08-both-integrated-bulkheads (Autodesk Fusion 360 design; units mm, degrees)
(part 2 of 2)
sketch "B Facet 180 Triangle 4" plane through (0, -75, 0) normal (0, -1, 0) x axis (-1, 0, 0)
  line L1 (124, -27.066) -> (60.9665, 27.066)
  line L2 (124, 27.066) -> (124, -27.066)
  line L3 (60.9665, 27.066) -> (124, 27.066)
  line L4 (120, -18.3583) -> (71.7639, 23.066)
  line L5 (120, 23.066) -> (120, -18.3583)
  line L6 (71.7639, 23.066) -> (120, 23.066)
  point P1 (0, 0)
  point P2 (60.9665, 27.066)
  point P3 (124, -27.066)
  point P4 (124, 27.066)
  dimension "d486" distance P1 P2 = 60.9665 (= "Linear Dimension-2")
  dimension "d487" distance P1 P2 = 27.066 (= "Linear Dimension-3")
  dimension "d488" distance P1 P3 = 124 (= "Linear Dimension-4")
  dimension "d489" distance P1 P3 = 27.066 (= "Linear Dimension-5")
  dimension "d490" distance P1 P4 = 124 (= "Linear Dimension-6")
  dimension "d491" distance P1 P4 = 27.066 (= "Linear Dimension-7")
  dimension "d492" = -4 (= "-memberWidth / 2")
extrude "Extrude15" cut sketch "B Facet 180 Triangle 4" profile of L5 L6 L4 against normal blind 4.7 (magnitude of "-( wall + 0.2 mm )")
fillet "Fillet5" radius 1.5 (= "apertureRadius")
work_plane "WorkPlane11" RotateAngle 135 ExtraOffset 0
work_plane "WorkPlane12" AlongDistance 75 (= "bodyWidth / 2") ExtraOffset 0
sketch "B Facet 225 Triangle 1" plane through (0, -53.033, -53.033) normal (0, -0.7071, -0.7071) x axis (1, 0, 0)
  line L1 (23.9949, -27.066) -> (62.2721, 27.066)
  line L2 (0.1814, 27.066) -> (23.9949, -27.066)
  line L3 (62.2721, 27.066) -> (0.1814, 27.066)
  line L4 (24.81, -18.9852) -> (54.5447, 23.066)
  line L5 (6.311, 23.066) -> (24.81, -18.9852)
  line L6 (54.5447, 23.066) -> (6.311, 23.066)
  point P1 (0, 0)
  point P2 (62.2721, 27.066)
  point P3 (23.9949, -27.066)
  point P4 (0.1814, 27.066)
  dimension "d501" distance P1 P2 = 62.2721 (= "Linear Dimension-2")
  dimension "d502" distance P1 P2 = 27.066 (= "Linear Dimension-3")
  dimension "d503" distance P1 P3 = 23.9949 (= "Linear Dimension-4")
  dimension "d504" distance P1 P3 = 27.066 (= "Linear Dimension-5")
  dimension "d505" distance P1 P4 = 0.1814 (= "Linear Dimension-6")
  dimension "d506" distance P1 P4 = 27.066 (= "Linear Dimension-7")
  dimension "d507" = 4 (= "memberWidth / 2")
extrude "Extrude16" cut sketch "B Facet 225 Triangle 1" profile of L5 L6 L4 against normal blind 4.7 (magnitude of "-( wall + 0.2 mm )")
sketch "B Facet 225 Triangle 2" plane through (0, -53.033, -53.033) normal (0, -0.7071, -0.7071) x axis (1, 0, 0)
  line L1 (0.1814, 27.066) -> (23.9949, -27.066)
  line L2 (-74.6684, -27.066) -> (0.1814, 27.066)
  line L3 (23.9949, -27.066) -> (-74.6684, -27.066)
  line L4 (-1.4863, 20.9235) -> (17.8653, -23.066)
  line L5 (-62.3117, -23.066) -> (-1.4863, 20.9235)
  line L6 (17.8653, -23.066) -> (-62.3117, -23.066)
  point P1 (0, 0)
  point P2 (23.9949, -27.066)
  point P3 (0.1814, 27.066)
  point P4 (-74.6684, -27.066)
  dimension "d510" distance P1 P2 = 23.9949 (= "Linear Dimension-2")
  dimension "d511" distance P1 P2 = 27.066 (= "Linear Dimension-3")
  dimension "d512" distance P1 P3 = 0.1814 (= "Linear Dimension-4")
  dimension "d513" distance P1 P3 = 27.066 (= "Linear Dimension-5")
  dimension "d514" distance P1 P4 = 74.6684 (= "Linear Dimension-6")
  dimension "d515" distance P1 P4 = 27.066 (= "Linear Dimension-7")
  dimension "d516" = -4 (= "-memberWidth / 2")
extrude "Extrude17" cut sketch "B Facet 225 Triangle 2" profile of L5 L6 L4 against normal blind 4.7 (magnitude of "-( wall + 0.2 mm )")
sketch "B Facet 225 Triangle 3" plane through (0, -53.033, -53.033) normal (0, -0.7071, -0.7071) x axis (1, 0, 0)
  line L1 (-74.6684, -27.066) -> (0.1814, 27.066)
  line L2 (-124, 27.066) -> (-74.6684, -27.066)
  line L3 (0.1814, 27.066) -> (-124, 27.066)
  line L4 (-74.1179, -21.7315) -> (-12.1753, 23.066)
  line L5 (-114.9429, 23.066) -> (-74.1179, -21.7315)
  line L6 (-12.1753, 23.066) -> (-114.9429, 23.066)
  point P1 (0, 0)
  point P2 (0.1814, 27.066)
  point P3 (-74.6684, -27.066)
  point P4 (-124, 27.066)
  dimension "d519" distance P1 P2 = 0.1814 (= "Linear Dimension-2")
  dimension "d520" distance P1 P2 = 27.066 (= "Linear Dimension-3")
  dimension "d521" distance P1 P3 = 74.6684 (= "Linear Dimension-4")
  dimension "d522" distance P1 P3 = 27.066 (= "Linear Dimension-5")
  dimension "d523" distance P1 P4 = 124 (= "Linear Dimension-6")
  dimension "d524" distance P1 P4 = 27.066 (= "Linear Dimension-7")
  dimension "d525" = 4 (= "memberWidth / 2")
extrude "Extrude18" cut sketch "B Facet 225 Triangle 3" profile of L5 L6 L4 against normal blind 4.7 (magnitude of "-( wall + 0.2 mm )")
sketch "B Facet 225 Triangle 4" plane through (0, -53.033, -53.033) normal (0, -0.7071, -0.7071) x axis (1, 0, 0)
  line L1 (-124, 27.066) -> (-74.6684, -27.066)
  line L2 (-124, -27.066) -> (-124, 27.066)
  line L3 (-74.6684, -27.066) -> (-124, -27.066)
  line L4 (-120, 16.7383) -> (-83.7255, -23.066)
  line L5 (-120, -23.066) -> (-120, 16.7383)
  line L6 (-83.7255, -23.066) -> (-120, -23.066)
  point P1 (0, 0)
  point P2 (-74.6684, -27.066)
  point P3 (-124, 27.066)
  point P4 (-124, -27.066)
  dimension "d528" distance P1 P2 = 74.6684 (= "Linear Dimension-2")
  dimension "d529" distance P1 P2 = 27.066 (= "Linear Dimension-3")
  dimension "d530" distance P1 P3 = 124 (= "Linear Dimension-4")
  dimension "d531" distance P1 P3 = 27.066 (= "Linear Dimension-5")
  dimension "d532" distance P1 P4 = 124 (= "Linear Dimension-6")
  dimension "d533" distance P1 P4 = 27.066 (= "Linear Dimension-7")
  dimension "d534" = -4 (= "-memberWidth / 2")
extrude "Extrude19" cut sketch "B Facet 225 Triangle 4" profile of L5 L6 L4 against normal blind 4.7 (magnitude of "-( wall + 0.2 mm )")
fillet "Fillet6" radius 1.5 (= "apertureRadius")
work_plane "WorkPlane13" RotateAngle 180 ExtraOffset 0
work_plane "WorkPlane14" AlongDistance 75 (= "bodyWidth / 2") ExtraOffset 0
sketch "B Facet 270 Triangle 1" plane through (0, 0, -75) normal (0, 0, -1) x axis (-1, 0, 0)
  line L1 (36.9655, 27.066) -> (-17.1665, -27.066)
  line L2 (53.4167, -27.066) -> (36.9655, 27.066)
  line L3 (-17.1665, -27.066) -> (53.4167, -27.066)
  line L4 (35.0777, 19.5214) -> (-7.5097, -23.066)
  line L5 (48.0205, -23.066) -> (35.0777, 19.5214)
  line L6 (-7.5097, -23.066) -> (48.0205, -23.066)
  point P1 (0, 0)
  point P2 (-17.1665, -27.066)
  point P3 (36.9655, 27.066)
  point P4 (53.4167, -27.066)
  dimension "d543" distance P1 P2 = 17.1665 (= "Linear Dimension-2")
  dimension "d544" distance P1 P2 = 27.066 (= "Linear Dimension-3")
  dimension "d545" distance P1 P3 = 36.9655 (= "Linear Dimension-4")
  dimension "d546" distance P1 P3 = 27.066 (= "Linear Dimension-5")
  dimension "d547" distance P1 P4 = 53.4167 (= "Linear Dimension-6")
  dimension "d548" distance P1 P4 = 27.066 (= "Linear Dimension-7")
  dimension "d549" = 4 (= "memberWidth / 2")
extrude "Extrude20" cut sketch "B Facet 270 Triangle 1" profile of L5 L6 L4 against normal blind 4.7 (magnitude of "-( wall + 0.2 mm )")
sketch "B Facet 270 Triangle 2" plane through (0, 0, -75) normal (0, 0, -1) x axis (-1, 0, 0)
  line L1 (53.4167, -27.066) -> (36.9655, 27.066)
  line L2 (124, 27.066) -> (53.4167, -27.066)
  line L3 (36.9655, 27.066) -> (124, 27.066)
  line L4 (55.5648, -20.3777) -> (42.3618, 23.066)
  line L5 (112.2115, 23.066) -> (55.5648, -20.3777)
  line L6 (42.3618, 23.066) -> (112.2115, 23.066)
  point P1 (0, 0)
  point P2 (36.9655, 27.066)
  point P3 (53.4167, -27.066)
  point P4 (124, 27.066)
  dimension "d552" distance P1 P2 = 36.9655 (= "Linear Dimension-2")
  dimension "d553" distance P1 P2 = 27.066 (= "Linear Dimension-3")
  dimension "d554" distance P1 P3 = 53.4167 (= "Linear Dimension-4")
  dimension "d555" distance P1 P3 = 27.066 (= "Linear Dimension-5")
  dimension "d556" distance P1 P4 = 124 (= "Linear Dimension-6")
  dimension "d557" distance P1 P4 = 27.066 (= "Linear Dimension-7")
  dimension "d558" = -4 (= "-memberWidth / 2")
extrude "Extrude21" cut sketch "B Facet 270 Triangle 2" profile of L5 L6 L4 against normal blind 4.7 (magnitude of "-( wall + 0.2 mm )")
sketch "B Facet 270 Triangle 3" plane through (0, 0, -75) normal (0, 0, -1) x axis (-1, 0, 0)
  line L1 (124, 27.066) -> (53.4167, -27.066)
  line L2 (124, -27.066) -> (124, 27.066)
  line L3 (53.4167, -27.066) -> (124, -27.066)
  line L4 (120, 18.9574) -> (65.2053, -23.066)
  line L5 (120, -23.066) -> (120, 18.9574)
  line L6 (65.2053, -23.066) -> (120, -23.066)
  point P1 (0, 0)
  point P2 (53.4167, -27.066)
  point P3 (124, 27.066)
  point P4 (124, -27.066)
  dimension "d561" distance P1 P2 = 53.4167 (= "Linear Dimension-2")
  dimension "d562" distance P1 P2 = 27.066 (= "Linear Dimension-3")
  dimension "d563" distance P1 P3 = 124 (= "Linear Dimension-4")
  dimension "d564" distance P1 P3 = 27.066 (= "Linear Dimension-5")
  dimension "d565" distance P1 P4 = 124 (= "Linear Dimension-6")
  dimension "d566" distance P1 P4 = 27.066 (= "Linear Dimension-7")
  dimension "d567" = 4 (= "memberWidth / 2")
extrude "Extrude22" cut sketch "B Facet 270 Triangle 3" profile of L5 L6 L4 against normal blind 4.7 (magnitude of "-( wall + 0.2 mm )")
fillet "Fillet7" radius 1.5 (= "apertureRadius")
work_plane "WorkPlane15" RotateAngle 225 ExtraOffset 0
work_plane "WorkPlane16" AlongDistance 75 (= "bodyWidth / 2") ExtraOffset 0
sketch "B Facet 315 Triangle 1" plane through (0, 53.033, -53.033) normal (0, 0.7071, -0.7071) x axis (1, 0, 0)
  line L1 (-82.0711, -27.066) -> (-43.7939, 27.066)
  line L2 (-124, 27.066) -> (-82.0711, -27.066)
  line L3 (-43.7939, 27.066) -> (-124, 27.066)
  line L4 (-82.2175, -20.3449) -> (-51.5213, 23.066)
  line L5 (-115.8422, 23.066) -> (-82.2175, -20.3449)
  line L6 (-51.5213, 23.066) -> (-115.8422, 23.066)
  point P1 (0, 0)
  point P2 (-43.7939, 27.066)
  point P3 (-82.0711, -27.066)
  point P4 (-124, 27.066)
  dimension "d576" distance P1 P2 = 43.7939 (= "Linear Dimension-2")
  dimension "d577" distance P1 P2 = 27.066 (= "Linear Dimension-3")
  dimension "d578" distance P1 P3 = 82.0711 (= "Linear Dimension-4")
  dimension "d579" distance P1 P3 = 27.066 (= "Linear Dimension-5")
  dimension "d580" distance P1 P4 = 124 (= "Linear Dimension-6")
  dimension "d581" distance P1 P4 = 27.066 (= "Linear Dimension-7")
  dimension "d582" = 4 (= "memberWidth / 2")
extrude "Extrude23" cut sketch "B Facet 315 Triangle 1" profile of L5 L6 L4 against normal blind 4.7 (magnitude of "-( wall + 0.2 mm )")
sketch "B Facet 315 Triangle 2" plane through (0, 53.033, -53.033) normal (0, 0.7071, -0.7071) x axis (1, 0, 0)
  line L1 (-124, 27.066) -> (-82.0711, -27.066)
  line L2 (-124, -27.066) -> (-124, 27.066)
  line L3 (-82.0711, -27.066) -> (-124, -27.066)
  line L4 (-120, 15.3697) -> (-90.2289, -23.066)
  line L5 (-120, -23.066) -> (-120, 15.3697)
  line L6 (-90.2289, -23.066) -> (-120, -23.066)
  point P1 (0, 0)
  point P2 (-82.0711, -27.066)
  point P3 (-124, 27.066)
  point P4 (-124, -27.066)
  dimension "d585" distance P1 P2 = 82.0711 (= "Linear Dimension-2")
  dimension "d586" distance P1 P2 = 27.066 (= "Linear Dimension-3")
  dimension "d587" distance P1 P3 = 124 (= "Linear Dimension-4")
  dimension "d588" distance P1 P3 = 27.066 (= "Linear Dimension-5")
  dimension "d589" distance P1 P4 = 124 (= "Linear Dimension-6")
  dimension "d590" distance P1 P4 = 27.066 (= "Linear Dimension-7")
  dimension "d591" = -4 (= "-memberWidth / 2")
extrude "Extrude24" cut sketch "B Facet 315 Triangle 2" profile of L5 L6 L4 against normal blind 4.7 (magnitude of "-( wall + 0.2 mm )")
fillet "Fillet8" radius 1.5 (= "apertureRadius")
work_plane "WorkPlane17" AlongDistance 0.5 (= "qFront") ExtraOffset 0
sketch "A Central Carrier sketch" plane through (0.3536, 0.3536, 0) normal (0.7071, 0.7071, 0) x axis (0, 0, 1)
  circle C1 centre (0, 0) radius 26
  dimension "d598" diameter C1 = 52 (= "carrierOD")
extrude "Extrude25" new body sketch "A Central Carrier sketch" along normal blind 18 (= "spokeDepth")
work_plane "WorkPlane18" AlongDistance 0.5 (= "qFront") ExtraOffset 0
sketch "A Spoke 1 Profile" plane through (0.3536, 0.3536, 0) normal (0.7071, 0.7071, 0) x axis (0, 0, 1)
  line L1 (37.3643, -145.3579) -> (-4.7984, -1.4054)
  line L2 (46.9611, -142.547) -> (37.3643, -145.3579)
  line L3 (4.7984, 1.4054) -> (46.9611, -142.547)
  line L4 (-4.7984, -1.4054) -> (4.7984, 1.4054)
  point P1 (0, 0)
  point P2 (-4.7984, -1.4054)
  point P3 (37.3643, -145.3579)
  point P4 (46.9611, -142.547)
  point P5 (4.7984, 1.4054)
  dimension "d603" distance P1 P2 = 4.7984 (= "Linear Dimension-2")
  dimension "d604" distance P1 P2 = 1.4054 (= "Linear Dimension-3")
  dimension "d605" distance P1 P3 = 37.3643 (= "Linear Dimension-4")
  dimension "d606" distance P1 P3 = 145.3579 (= "Linear Dimension-5")
  dimension "d607" distance P1 P4 = 46.9611 (= "Linear Dimension-6")
  dimension "d608" distance P1 P4 = 142.547 (= "Linear Dimension-7")
  dimension "d609" distance P1 P5 = 4.7984 (= "Linear Dimension-8")
  dimension "d610" distance P1 P5 = 1.4054 (= "Linear Dimension-9")
extrude "Extrude26" add sketch "A Spoke 1 Profile" along normal blind 18 (= "spokeDepth")
sketch "A Spoke 2 Profile" plane through (0.3536, 0.3536, 0) normal (0.7071, 0.7071, 0) x axis (0, 0, 1)
  line L1 (126.9012, -80.1317) -> (-2.5272, -4.3143)
  line L2 (131.9557, -71.5031) -> (126.9012, -80.1317)
  line L3 (2.5272, 4.3143) -> (131.9557, -71.5031)
  line L4 (-2.5272, -4.3143) -> (2.5272, 4.3143)
  point P1 (0, 0)
  point P2 (-2.5272, -4.3143)
  point P3 (126.9012, -80.1317)
  point P4 (131.9557, -71.5031)
  point P5 (2.5272, 4.3143)
  dimension "d613" distance P1 P2 = 2.5272 (= "Linear Dimension-2")
  dimension "d614" distance P1 P2 = 4.3143 (= "Linear Dimension-3")
  dimension "d615" distance P1 P3 = 126.9012 (= "Linear Dimension-4")
  dimension "d616" distance P1 P3 = 80.1317 (= "Linear Dimension-5")
  dimension "d617" distance P1 P4 = 131.9557 (= "Linear Dimension-6")
  dimension "d618" distance P1 P4 = 71.5031 (= "Linear Dimension-7")
  dimension "d619" distance P1 P5 = 2.5272 (= "Linear Dimension-8")
  dimension "d620" distance P1 P5 = 4.3143 (= "Linear Dimension-9")
extrude "Extrude27" add sketch "A Spoke 2 Profile" along normal blind 18 (= "spokeDepth")
sketch "A Spoke 3 Profile" plane through (0.3536, 0.3536, 0) normal (0.7071, 0.7071, 0) x axis (0, 0, 1)
  line L1 (131.9557, 71.5031) -> (2.5272, -4.3143)
  line L2 (126.9012, 80.1317) -> (131.9557, 71.5031)
  line L3 (-2.5272, 4.3143) -> (126.9012, 80.1317)
  line L4 (2.5272, -4.3143) -> (-2.5272, 4.3143)
  point P1 (0, 0)
  point P2 (2.5272, -4.3143)
  point P3 (131.9557, 71.5031)
  point P4 (126.9012, 80.1317)
  point P5 (-2.5272, 4.3143)
  dimension "d623" distance P1 P2 = 2.5272 (= "Linear Dimension-2")
  dimension "d624" distance P1 P2 = 4.3143 (= "Linear Dimension-3")
  dimension "d625" distance P1 P3 = 131.9557 (= "Linear Dimension-4")
  dimension "d626" distance P1 P3 = 71.5031 (= "Linear Dimension-5")
  dimension "d627" distance P1 P4 = 126.9012 (= "Linear Dimension-6")
  dimension "d628" distance P1 P4 = 80.1317 (= "Linear Dimension-7")
  dimension "d629" distance P1 P5 = 2.5272 (= "Linear Dimension-8")
  dimension "d630" distance P1 P5 = 4.3143 (= "Linear Dimension-9")
extrude "Extrude28" add sketch "A Spoke 3 Profile" along normal blind 18 (= "spokeDepth")
sketch "A Spoke 4 Profile" plane through (0.3536, 0.3536, 0) normal (0.7071, 0.7071, 0) x axis (0, 0, 1)
  line L1 (46.9611, 142.547) -> (4.7984, -1.4054)
  line L2 (37.3643, 145.3579) -> (46.9611, 142.547)
  line L3 (-4.7984, 1.4054) -> (37.3643, 145.3579)
  line L4 (4.7984, -1.4054) -> (-4.7984, 1.4054)
  point P1 (0, 0)
  point P2 (4.7984, -1.4054)
  point P3 (46.9611, 142.547)
  point P4 (37.3643, 145.3579)
  point P5 (-4.7984, 1.4054)
  dimension "d633" distance P1 P2 = 4.7984 (= "Linear Dimension-2")
  dimension "d634" distance P1 P2 = 1.4054 (= "Linear Dimension-3")
  dimension "d635" distance P1 P3 = 46.9611 (= "Linear Dimension-4")
  dimension "d636" distance P1 P3 = 142.547 (= "Linear Dimension-5")
  dimension "d637" distance P1 P4 = 37.3643 (= "Linear Dimension-6")
  dimension "d638" distance P1 P4 = 145.3579 (= "Linear Dimension-7")
  dimension "d639" distance P1 P5 = 4.7984 (= "Linear Dimension-8")
  dimension "d640" distance P1 P5 = 1.4054 (= "Linear Dimension-9")
extrude "Extrude29" add sketch "A Spoke 4 Profile" along normal blind 18 (= "spokeDepth")
sketch "A Spoke 5 Profile" plane through (0.3536, 0.3536, 0) normal (0.7071, 0.7071, 0) x axis (0, 0, 1)
  line L1 (-37.3643, 145.3579) -> (4.7984, 1.4054)
  line L2 (-46.9611, 142.547) -> (-37.3643, 145.3579)
  line L3 (-4.7984, -1.4054) -> (-46.9611, 142.547)
  line L4 (4.7984, 1.4054) -> (-4.7984, -1.4054)
  point P1 (0, 0)
  point P2 (4.7984, 1.4054)
  point P3 (-37.3643, 145.3579)
  point P4 (-46.9611, 142.547)
  point P5 (-4.7984, -1.4054)
  dimension "d643" distance P1 P2 = 4.7984 (= "Linear Dimension-2")
  dimension "d644" distance P1 P2 = 1.4054 (= "Linear Dimension-3")
  dimension "d645" distance P1 P3 = 37.3643 (= "Linear Dimension-4")
  dimension "d646" distance P1 P3 = 145.3579 (= "Linear Dimension-5")
  dimension "d647" distance P1 P4 = 46.9611 (= "Linear Dimension-6")
  dimension "d648" distance P1 P4 = 142.547 (= "Linear Dimension-7")
  dimension "d649" distance P1 P5 = 4.7984 (= "Linear Dimension-8")
  dimension "d650" distance P1 P5 = 1.4054 (= "Linear Dimension-9")
extrude "Extrude30" add sketch "A Spoke 5 Profile" along normal blind 18 (= "spokeDepth")
sketch "A Spoke 6 Profile" plane through (0.3536, 0.3536, 0) normal (0.7071, 0.7071, 0) x axis (0, 0, 1)
  line L1 (-126.9012, 80.1317) -> (2.5272, 4.3143)
  line L2 (-131.9557, 71.5031) -> (-126.9012, 80.1317)
  line L3 (-2.5272, -4.3143) -> (-131.9557, 71.5031)
  line L4 (2.5272, 4.3143) -> (-2.5272, -4.3143)
  point P1 (0, 0)
  point P2 (2.5272, 4.3143)
  point P3 (-126.9012, 80.1317)
  point P4 (-131.9557, 71.5031)
  point P5 (-2.5272, -4.3143)
  dimension "d653" distance P1 P2 = 2.5272 (= "Linear Dimension-2")
  dimension "d654" distance P1 P2 = 4.3143 (= "Linear Dimension-3")
  dimension "d655" distance P1 P3 = 126.9012 (= "Linear Dimension-4")
  dimension "d656" distance P1 P3 = 80.1317 (= "Linear Dimension-5")
  dimension "d657" distance P1 P4 = 131.9557 (= "Linear Dimension-6")
  dimension "d658" distance P1 P4 = 71.5031 (= "Linear Dimension-7")
  dimension "d659" distance P1 P5 = 2.5272 (= "Linear Dimension-8")
  dimension "d660" distance P1 P5 = 4.3143 (= "Linear Dimension-9")
extrude "Extrude31" add sketch "A Spoke 6 Profile" along normal blind 18 (= "spokeDepth")
sketch "A Spoke 7 Profile" plane through (0.3536, 0.3536, 0) normal (0.7071, 0.7071, 0) x axis (0, 0, 1)
  line L1 (-131.9557, -71.5031) -> (-2.5272, 4.3143)
  line L2 (-126.9012, -80.1317) -> (-131.9557, -71.5031)
  line L3 (2.5272, -4.3143) -> (-126.9012, -80.1317)
  line L4 (-2.5272, 4.3143) -> (2.5272, -4.3143)
  point P1 (0, 0)
  point P2 (-2.5272, 4.3143)
  point P3 (-131.9557, -71.5031)
  point P4 (-126.9012, -80.1317)
  point P5 (2.5272, -4.3143)
  dimension "d663" distance P1 P2 = 2.5272 (= "Linear Dimension-2")
  dimension "d664" distance P1 P2 = 4.3143 (= "Linear Dimension-3")
  dimension "d665" distance P1 P3 = 131.9557 (= "Linear Dimension-4")
  dimension "d666" distance P1 P3 = 71.5031 (= "Linear Dimension-5")
  dimension "d667" distance P1 P4 = 126.9012 (= "Linear Dimension-6")
  dimension "d668" distance P1 P4 = 80.1317 (= "Linear Dimension-7")
  dimension "d669" distance P1 P5 = 2.5272 (= "Linear Dimension-8")
  dimension "d670" distance P1 P5 = 4.3143 (= "Linear Dimension-9")
extrude "Extrude32" add sketch "A Spoke 7 Profile" along normal blind 18 (= "spokeDepth")
sketch "A Spoke 8 Profile" plane through (0.3536, 0.3536, 0) normal (0.7071, 0.7071, 0) x axis (0, 0, 1)
  line L1 (-46.9611, -142.547) -> (-4.7984, 1.4054)
  line L2 (-37.3643, -145.3579) -> (-46.9611, -142.547)
  line L3 (4.7984, 1.4054) -> (-37.3643, -145.3579)
  line L4 (-4.7984, 1.4054) -> (4.7984, 1.4054)
  point P1 (0, 0)
  point P2 (-4.7984, 1.4054)
  point P3 (-46.9611, -142.547)
  point P4 (-37.3643, -145.3579)
  point P5 (4.7984, 1.4054)
  dimension "d673" distance P1 P2 = 4.7984 (= "Linear Dimension-2")
  dimension "d674" distance P1 P2 = 1.4054 (= "Linear Dimension-3")
  dimension "d675" distance P1 P3 = 46.9611 (= "Linear Dimension-4")
  dimension "d676" distance P1 P3 = 142.547 (= "Linear Dimension-5")
  dimension "d677" distance P1 P4 = 37.3643 (= "Linear Dimension-6")
  dimension "d678" distance P1 P4 = 145.3579 (= "Linear Dimension-7")
  dimension "d679" distance P1 P5 = 4.7984 (= "Linear Dimension-8")
  dimension "d680" distance P1 P5 = 1.4054 (= "Linear Dimension-9")
extrude "Extrude33" add sketch "A Spoke 8 Profile" along normal blind 18 (= "spokeDepth")
sketch "Spoke Outer Envelope" plane through (0, 0, 0) normal (1, 0, 0) x axis (0, 0, -1)
  line L1 (31.066, 75) -> (75, 31.066)
  line L2 (-31.066, 75) -> (31.066, 75)
  line L3 (-75, 31.066) -> (-31.066, 75)
  line L4 (-75, -31.066) -> (-75, 31.066)
  line L5 (-31.066, -75) -> (-75, -31.066)
  line L6 (31.066, -75) -> (-31.066, -75)
  line L7 (75, -31.066) -> (31.066, -75)
  line L8 (75, 31.066) -> (75, -31.066)
  point P1 (0, 0)
  point P10 (0, 0)
  point P3 (31.066, 75)
  point P8 (31.066, -75)
  coincident P1 P10
  horizontal L2
  dimension "d683" distance P3 P8 = 150 (= "bodyWidth")
extrude "Extrude34" sketch "Spoke Outer Envelope" distance 260 (= "bodyLength")
fillet "Fillet9" radius 1 (= "rootRadius")
work_plane "WorkPlane19" AlongDistance 10.6 (= "qFrontBack") ExtraOffset 0
sketch "A Rear Carrier Clearance sketch" plane through (7.4953, 7.4953, 0) normal (0.7071, 0.7071, 0) x axis (0, 0, 1)
  circle C1 centre (0, 0) radius 23
  dimension "d690" diameter C1 = 46 (= "rearCarrierClearance")
extrude "Extrude35" cut sketch "A Rear Carrier Clearance sketch" along normal blind 18 (= "spokeDepth")
work_plane "WorkPlane20" AlongDistance 0.5 (= "qFront") ExtraOffset 0
sketch "A Seal Relief sketch" plane through (0.3536, 0.3536, 0) normal (0.7071, 0.7071, 0) x axis (0, 0, 1)
  circle C1 centre (0, 0) radius 9.75
  dimension "d695" diameter C1 = 19.5 (= "raceRelief")
extrude "Extrude36" cut sketch "A Seal Relief sketch" along normal blind 10.1 (= "frontSeatDepth + shoulder")
work_plane "WorkPlane21" AlongDistance 0.5 (= "qFront") ExtraOffset 0
sketch "A Front Bearing Seat sketch" plane through (0.3536, 0.3536, 0) normal (0.7071, 0.7071, 0) x axis (0, 0, 1)
  circle C1 centre (0, 0) radius 11.1
  dimension "d700" diameter C1 = 22.2 (= "seatDiameter")
extrude "Extrude37" cut sketch "A Front Bearing Seat sketch" along normal blind 7.1 (= "frontSeatDepth")
work_plane "WorkPlane22" AlongDistance 0.5 (= "qFront") ExtraOffset 0
sketch "A Support Bolt seed" plane through (0.3536, 0.3536, 0) normal (0.7071, 0.7071, 0) x axis (0, 0, 1)
  line L1 (17, 0) -> (0, 0)
  circle C1 centre (17, 0) radius 1.65
  point P1 (0, 0)
  point P2 (17, 0)
  horizontal L1
  dimension "d705" distance P1 P2 = 17 (= "supportCircle / 2")
  dimension "d706" diameter C1 = 3.3 (= "m3Clearance")
extrude "Extrude38" cut sketch "A Support Bolt seed" profile of C1 along normal blind 10.1 (= "frontSeatDepth + shoulder")
circular_pattern "C-Pattern1" TotalAngle 360
work_plane "WorkPlane23" AlongDistance 0.5 (= "qFront") ExtraOffset 0
sketch "A Front Bearing Boss sketch" plane through (0.3536, 0.3536, 0) normal (0.7071, 0.7071, 0) x axis (0, 0, 1)
  circle C1 centre (0, 0) radius 22
  dimension "d713" diameter C1 = 44 (= "coreOD")
chamfer "Chamfer1" distance 0.4 (= "entryChamfer")
work_plane "WorkPlane24" AlongDistance 75 (= "bodyWidth / 2") ExtraOffset 0
sketch "A Collar Driver Corridors" plane through (0, 0, 75) normal (0, 0, 1) x axis (1, 0, 0)
  circle C1 centre (6.7175, 15.9099) radius 3
  circle C2 centre (15.9099, 6.7175) radius 3
  point P1 (0, 0)
  point P2 (6.7175, 15.9099)
  point P3 (15.9099, 6.7175)
  dimension "d717" distance P1 P2 = 6.7175 (= "abs(( 16 mm + ( -6.5 mm ) ) / sqrt(2))")
  dimension "d718" distance P1 P2 = 15.9099 (= "abs(( 16 mm - ( -6.5 mm ) ) / sqrt(2))")
  dimension "d719" diameter C1 = 6
  dimension "d720" distance P1 P3 = 15.9099 (= "abs(( 16 mm + ( 6.5 mm ) ) / sqrt(2))")
  dimension "d721" distance P1 P3 = 6.7175 (= "abs(( 16 mm - ( 6.5 mm ) ) / sqrt(2))")
  dimension "d722" diameter C2 = 6
extrude "Extrude39" cut sketch "A Collar Driver Corridors" against normal blind 75 (magnitude of "-( bodyWidth / 2 )")
work_plane "WorkPlane17" ExtraOffset 0
sketch "B Central Carrier sketch" plane through (-0.3536, -0.3536, 0) normal (0.7071, 0.7071, 0) x axis (0, 0, 1)
  circle C1 centre (0, 0) radius 38
  dimension "d727" diameter C1 = 76 (= "mountOD")
extrude "Extrude25" new body sketch "B Central Carrier sketch" no distance stored
work_plane "WorkPlane18" ExtraOffset 0
sketch "B Spoke 1 Profile" plane through (-0.3536, -0.3536, 0) normal (0.7071, 0.7071, 0) x axis (0, 0, 1)
  line L1 (37.3643, -145.3579) -> (-4.7984, -1.4054)
  line L2 (46.9611, -142.547) -> (37.3643, -145.3579)
  line L3 (4.7984, 1.4054) -> (46.9611, -142.547)
  line L4 (-4.7984, -1.4054) -> (4.7984, 1.4054)
  point P1 (0, 0)
  point P2 (-4.7984, -1.4054)
  point P3 (37.3643, -145.3579)
  point P4 (46.9611, -142.547)
  point P5 (4.7984, 1.4054)
  dimension "d732" distance P1 P2 = 4.7984 (= "Linear Dimension-2")
  dimension "d733" distance P1 P2 = 1.4054 (= "Linear Dimension-3")
  dimension "d734" distance P1 P3 = 37.3643 (= "Linear Dimension-4")
  dimension "d735" distance P1 P3 = 145.3579 (= "Linear Dimension-5")
  dimension "d736" distance P1 P4 = 46.9611 (= "Linear Dimension-6")
  dimension "d737" distance P1 P4 = 142.547 (= "Linear Dimension-7")
  dimension "d738" distance P1 P5 = 4.7984 (= "Linear Dimension-8")
  dimension "d739" distance P1 P5 = 1.4054 (= "Linear Dimension-9")
extrude "Extrude26" add sketch "B Spoke 1 Profile" no distance stored
sketch "B Spoke 2 Profile" plane through (-0.3536, -0.3536, 0) normal (0.7071, 0.7071, 0) x axis (0, 0, 1)
  line L1 (126.9012, -80.1317) -> (-2.5272, -4.3143)
  line L2 (131.9557, -71.5031) -> (126.9012, -80.1317)
  line L3 (2.5272, 4.3143) -> (131.9557, -71.5031)
  line L4 (-2.5272, -4.3143) -> (2.5272, 4.3143)
  point P1 (0, 0)
  point P2 (-2.5272, -4.3143)
  point P3 (126.9012, -80.1317)
  point P4 (131.9557, -71.5031)
  point P5 (2.5272, 4.3143)
  dimension "d742" distance P1 P2 = 2.5272 (= "Linear Dimension-2")
  dimension "d743" distance P1 P2 = 4.3143 (= "Linear Dimension-3")
  dimension "d744" distance P1 P3 = 126.9012 (= "Linear Dimension-4")
  dimension "d745" distance P1 P3 = 80.1317 (= "Linear Dimension-5")
  dimension "d746" distance P1 P4 = 131.9557 (= "Linear Dimension-6")
  dimension "d747" distance P1 P4 = 71.5031 (= "Linear Dimension-7")
  dimension "d748" distance P1 P5 = 2.5272 (= "Linear Dimension-8")
  dimension "d749" distance P1 P5 = 4.3143 (= "Linear Dimension-9")
extrude "Extrude27" add sketch "B Spoke 2 Profile" no distance stored
sketch "B Spoke 3 Profile" plane through (-0.3536, -0.3536, 0) normal (0.7071, 0.7071, 0) x axis (0, 0, 1)
  line L1 (131.9557, 71.5031) -> (2.5272, -4.3143)
  line L2 (126.9012, 80.1317) -> (131.9557, 71.5031)
  line L3 (-2.5272, 4.3143) -> (126.9012, 80.1317)
  line L4 (2.5272, -4.3143) -> (-2.5272, 4.3143)
  point P1 (0, 0)
  point P2 (2.5272, -4.3143)
  point P3 (131.9557, 71.5031)
  point P4 (126.9012, 80.1317)
  point P5 (-2.5272, 4.3143)
  dimension "d752" distance P1 P2 = 2.5272 (= "Linear Dimension-2")
  dimension "d753" distance P1 P2 = 4.3143 (= "Linear Dimension-3")
  dimension "d754" distance P1 P3 = 131.9557 (= "Linear Dimension-4")
  dimension "d755" distance P1 P3 = 71.5031 (= "Linear Dimension-5")
  dimension "d756" distance P1 P4 = 126.9012 (= "Linear Dimension-6")
  dimension "d757" distance P1 P4 = 80.1317 (= "Linear Dimension-7")
  dimension "d758" distance P1 P5 = 2.5272 (= "Linear Dimension-8")
  dimension "d759" distance P1 P5 = 4.3143 (= "Linear Dimension-9")
extrude "Extrude28" add sketch "B Spoke 3 Profile" no distance stored
sketch "B Spoke 4 Profile" plane through (-0.3536, -0.3536, 0) normal (0.7071, 0.7071, 0) x axis (0, 0, 1)
  line L1 (46.9611, 142.547) -> (4.7984, -1.4054)
  line L2 (37.3643, 145.3579) -> (46.9611, 142.547)
  line L3 (-4.7984, 1.4054) -> (37.3643, 145.3579)
  line L4 (4.7984, -1.4054) -> (-4.7984, 1.4054)
  point P1 (0, 0)
  point P2 (4.7984, -1.4054)
  point P3 (46.9611, 142.547)
  point P4 (37.3643, 145.3579)
  point P5 (-4.7984, 1.4054)
  dimension "d762" distance P1 P2 = 4.7984 (= "Linear Dimension-2")
  dimension "d763" distance P1 P2 = 1.4054 (= "Linear Dimension-3")
  dimension "d764" distance P1 P3 = 46.9611 (= "Linear Dimension-4")
  dimension "d765" distance P1 P3 = 142.547 (= "Linear Dimension-5")
  dimension "d766" distance P1 P4 = 37.3643 (= "Linear Dimension-6")
  dimension "d767" distance P1 P4 = 145.3579 (= "Linear Dimension-7")
  dimension "d768" distance P1 P5 = 4.7984 (= "Linear Dimension-8")
  dimension "d769" distance P1 P5 = 1.4054 (= "Linear Dimension-9")
extrude "Extrude29" add sketch "B Spoke 4 Profile" no distance stored
sketch "B Spoke 5 Profile" plane through (-0.3536, -0.3536, 0) normal (0.7071, 0.7071, 0) x axis (0, 0, 1)
  line L1 (-37.3643, 145.3579) -> (4.7984, 1.4054)
  line L2 (-46.9611, 142.547) -> (-37.3643, 145.3579)
  line L3 (-4.7984, -1.4054) -> (-46.9611, 142.547)
  line L4 (4.7984, 1.4054) -> (-4.7984, -1.4054)
  point P1 (0, 0)
  point P2 (4.7984, 1.4054)
  point P3 (-37.3643, 145.3579)
  point P4 (-46.9611, 142.547)
  point P5 (-4.7984, -1.4054)
  dimension "d772" distance P1 P2 = 4.7984 (= "Linear Dimension-2")
  dimension "d773" distance P1 P2 = 1.4054 (= "Linear Dimension-3")
  dimension "d774" distance P1 P3 = 37.3643 (= "Linear Dimension-4")
  dimension "d775" distance P1 P3 = 145.3579 (= "Linear Dimension-5")
  dimension "d776" distance P1 P4 = 46.9611 (= "Linear Dimension-6")
  dimension "d777" distance P1 P4 = 142.547 (= "Linear Dimension-7")
  dimension "d778" distance P1 P5 = 4.7984 (= "Linear Dimension-8")
  dimension "d779" distance P1 P5 = 1.4054 (= "Linear Dimension-9")
extrude "Extrude30" add sketch "B Spoke 5 Profile" no distance stored
sketch "B Spoke 6 Profile" plane through (-0.3536, -0.3536, 0) normal (0.7071, 0.7071, 0) x axis (0, 0, 1)
  line L1 (-126.9012, 80.1317) -> (2.5272, 4.3143)
  line L2 (-131.9557, 71.5031) -> (-126.9012, 80.1317)
  line L3 (-2.5272, -4.3143) -> (-131.9557, 71.5031)
  line L4 (2.5272, 4.3143) -> (-2.5272, -4.3143)
  point P1 (0, 0)
  point P2 (2.5272, 4.3143)
  point P3 (-126.9012, 80.1317)
  point P4 (-131.9557, 71.5031)
  point P5 (-2.5272, -4.3143)
  dimension "d782" distance P1 P2 = 2.5272 (= "Linear Dimension-2")
  dimension "d783" distance P1 P2 = 4.3143 (= "Linear Dimension-3")
  dimension "d784" distance P1 P3 = 126.9012 (= "Linear Dimension-4")
  dimension "d785" distance P1 P3 = 80.1317 (= "Linear Dimension-5")
  dimension "d786" distance P1 P4 = 131.9557 (= "Linear Dimension-6")
  dimension "d787" distance P1 P4 = 71.5031 (= "Linear Dimension-7")
  dimension "d788" distance P1 P5 = 2.5272 (= "Linear Dimension-8")
  dimension "d789" distance P1 P5 = 4.3143 (= "Linear Dimension-9")
extrude "Extrude31" add sketch "B Spoke 6 Profile" no distance stored
sketch "B Spoke 7 Profile" plane through (-0.3536, -0.3536, 0) normal (0.7071, 0.7071, 0) x axis (0, 0, 1)
  line L1 (-131.9557, -71.5031) -> (-2.5272, 4.3143)
  line L2 (-126.9012, -80.1317) -> (-131.9557, -71.5031)
  line L3 (2.5272, -4.3143) -> (-126.9012, -80.1317)
  line L4 (-2.5272, 4.3143) -> (2.5272, -4.3143)
  point P1 (0, 0)
  point P2 (-2.5272, 4.3143)
  point P3 (-131.9557, -71.5031)
  point P4 (-126.9012, -80.1317)
  point P5 (2.5272, -4.3143)
  dimension "d792" distance P1 P2 = 2.5272 (= "Linear Dimension-2")
  dimension "d793" distance P1 P2 = 4.3143 (= "Linear Dimension-3")
  dimension "d794" distance P1 P3 = 131.9557 (= "Linear Dimension-4")
  dimension "d795" distance P1 P3 = 71.5031 (= "Linear Dimension-5")
  dimension "d796" distance P1 P4 = 126.9012 (= "Linear Dimension-6")
  dimension "d797" distance P1 P4 = 80.1317 (= "Linear Dimension-7")
  dimension "d798" distance P1 P5 = 2.5272 (= "Linear Dimension-8")
  dimension "d799" distance P1 P5 = 4.3143 (= "Linear Dimension-9")
extrude "Extrude32" add sketch "B Spoke 7 Profile" no distance stored
sketch "B Spoke 8 Profile" plane through (-0.3536, -0.3536, 0) normal (0.7071, 0.7071, 0) x axis (0, 0, 1)
  line L1 (-46.9611, -142.547) -> (-4.7984, 1.4054)
  line L2 (-37.3643, -145.3579) -> (-46.9611, -142.547)
  line L3 (4.7984, 1.4054) -> (-37.3643, -145.3579)
  line L4 (-4.7984, 1.4054) -> (4.7984, 1.4054)
  point P1 (0, 0)
  point P2 (-4.7984, 1.4054)
  point P3 (-46.9611, -142.547)
  point P4 (-37.3643, -145.3579)
  point P5 (4.7984, 1.4054)
  dimension "d802" distance P1 P2 = 4.7984 (= "Linear Dimension-2")
  dimension "d803" distance P1 P2 = 1.4054 (= "Linear Dimension-3")
  dimension "d804" distance P1 P3 = 46.9611 (= "Linear Dimension-4")
  dimension "d805" distance P1 P3 = 142.547 (= "Linear Dimension-5")
  dimension "d806" distance P1 P4 = 37.3643 (= "Linear Dimension-6")
  dimension "d807" distance P1 P4 = 145.3579 (= "Linear Dimension-7")
  dimension "d808" distance P1 P5 = 4.7984 (= "Linear Dimension-8")
  dimension "d809" distance P1 P5 = 1.4054 (= "Linear Dimension-9")
extrude "Extrude33" add sketch "B Spoke 8 Profile" no distance stored
sketch "Spoke Outer Envelope" plane through (0, 0, 0) normal (1, 0, 0) x axis (0, 0, -1)
  line L1 (31.066, 75) -> (75, 31.066)
  line L2 (-31.066, 75) -> (31.066, 75)
  line L3 (-75, 31.066) -> (-31.066, 75)
  line L4 (-75, -31.066) -> (-75, 31.066)
  line L5 (-31.066, -75) -> (-75, -31.066)
  line L6 (31.066, -75) -> (-31.066, -75)
  line L7 (75, -31.066) -> (31.066, -75)
  line L8 (75, 31.066) -> (75, -31.066)
  point P1 (0, 0)
  point P10 (0, 0)
  point P3 (31.066, 75)
  point P8 (31.066, -75)
  coincident P1 P10
  horizontal L2
  dimension "d812" distance P3 P8 = 150 (= "bodyWidth")
extrude "Extrude34" sketch "Spoke Outer Envelope" distance 260 (= "bodyLength")
fillet "Fillet9" radius 1 (= "rootRadius")
work_plane "WorkPlane19" ExtraOffset 0
sketch "B Open Hub Cavity sketch" plane through (-0.3536, -0.3536, 0) normal (0.7071, 0.7071, 0) x axis (0, 0, 1)
  circle C1 centre (0, 0) radius 25.15
  dimension "d819" diameter C1 = 50.3 (= "mountOpening")
extrude "Extrude35" cut sketch "B Open Hub Cavity sketch" no distance stored
work_plane "WorkPlane20" ExtraOffset 0
sketch "B Four Mount Holes" plane through (-0.3536, -0.3536, 0) normal (0.7071, 0.7071, 0) x axis (0, 0, 1)
  circle C1 centre (22.6274, 22.6274) radius 2.15
  circle C2 centre (-22.6274, 22.6274) radius 2.15
  circle C3 centre (-22.6274, -22.6274) radius 2.15
  circle C4 centre (22.6274, -22.6274) radius 2.15
  point P1 (0, 0)
  point P2 (22.6274, 22.6274)
  point P3 (-22.6274, 22.6274)
  point P4 (-22.6274, -22.6274)
  point P5 (22.6274, -22.6274)
  dimension "d824" distance P1 P2 = 22.6274 (= "abs(mountCircle / ( 2 * sqrt(2) ))")
  dimension "d825" distance P1 P2 = 22.6274 (= "abs(mountCircle / ( 2 * sqrt(2) ))")
  dimension "d826" diameter C1 = 4.3 (= "m4Clearance")
  dimension "d827" distance P1 P3 = 22.6274 (= "abs(-mountCircle / ( 2 * sqrt(2) ))")
  dimension "d828" distance P1 P3 = 22.6274 (= "abs(mountCircle / ( 2 * sqrt(2) ))")
  dimension "d829" diameter C2 = 4.3 (= "m4Clearance")
  dimension "d830" distance P1 P4 = 22.6274 (= "abs(-mountCircle / ( 2 * sqrt(2) ))")
  dimension "d831" distance P1 P4 = 22.6274 (= "abs(-mountCircle / ( 2 * sqrt(2) ))")
  dimension "d832" diameter C3 = 4.3 (= "m4Clearance")
  dimension "d833" distance P1 P5 = 22.6274 (= "abs(mountCircle / ( 2 * sqrt(2) ))")
  dimension "d834" distance P1 P5 = 22.6274 (= "abs(-mountCircle / ( 2 * sqrt(2) ))")
  dimension "d835" diameter C4 = 4.3 (= "m4Clearance")
extrude "Extrude36" cut sketch "B Four Mount Holes" no distance stored
sketch "B M4 Nut Pocket 1" plane through (-0.3536, -0.3536, 0) normal (0.7071, 0.7071, 0) x axis (0, 0, 1)
  line L1 (24.7059, 26.2274) -> (26.7843, 22.6274)
  line L2 (20.549, 26.2274) -> (24.7059, 26.2274)
  line L3 (18.4705, 22.6274) -> (20.549, 26.2274)
  line L4 (20.549, 19.0274) -> (18.4705, 22.6274)
  line L5 (24.7059, 19.0274) -> (20.549, 19.0274)
  line L6 (26.7843, 22.6274) -> (24.7059, 19.0274)
  circle C1 centre (22.6274, 22.6274) radius 4.1569
  point P3 (26.7843, 22.6274)
  point P4 (24.7059, 26.2274)
  point P5 (20.549, 26.2274)
  point P6 (18.4705, 22.6274)
  point P7 (20.549, 19.0274)
  point P8 (24.7059, 19.0274)
  point P1 (0, 0)
  point P2 (22.6274, 22.6274)
  coincident C1 P3
  coincident C1 P4
  coincident C1 P5
  coincident C1 P6
  coincident C1 P7
  coincident C1 P8
  equal L1 L2
  equal L1 L3
  equal L1 L4
  equal L1 L5
  equal L1 L6
  horizontal L2
  dimension "d838" distance P1 P2 = 22.6274 (= "abs(mountCircle / ( 2 * sqrt(2) ))")
  dimension "d839" distance P1 P2 = 22.6274 (= "abs(mountCircle / ( 2 * sqrt(2) ))")
  dimension "d840" diameter C1 = 8.3138 (= "2 * ( nutAF ) / sqrt(3)")
extrude "Extrude37" cut sketch "B M4 Nut Pocket 1" profile of L1 L2 L3 L4 L5 L6 no distance stored
sketch "B M4 Nut Pocket 2" plane through (-0.3536, -0.3536, 0) normal (0.7071, 0.7071, 0) x axis (0, 0, 1)
  line L1 (-20.549, 26.2274) -> (-18.4705, 22.6274)
  line L2 (-24.7059, 26.2274) -> (-20.549, 26.2274)
  line L3 (-26.7843, 22.6274) -> (-24.7059, 26.2274)
  line L4 (-24.7059, 19.0274) -> (-26.7843, 22.6274)
  line L5 (-20.549, 19.0274) -> (-24.7059, 19.0274)
  line L6 (-18.4705, 22.6274) -> (-20.549, 19.0274)
  circle C1 centre (-22.6274, 22.6274) radius 4.1569
  point P3 (-18.4705, 22.6274)
  point P4 (-20.549, 26.2274)
  point P5 (-24.7059, 26.2274)
  point P6 (-26.7843, 22.6274)
  point P7 (-24.7059, 19.0274)
  point P8 (-20.549, 19.0274)
  point P1 (0, 0)
  point P2 (-22.6274, 22.6274)
  coincident C1 P3
  coincident C1 P4
  coincident C1 P5
  coincident C1 P6
  coincident C1 P7
  coincident C1 P8
  equal L1 L2
  equal L1 L3
  equal L1 L4
  equal L1 L5
  equal L1 L6
  horizontal L2
  dimension "d843" distance P1 P2 = 22.6274 (= "abs(-mountCircle / ( 2 * sqrt(2) ))")
  dimension "d844" distance P1 P2 = 22.6274 (= "abs(mountCircle / ( 2 * sqrt(2) ))")
  dimension "d845" diameter C1 = 8.3138 (= "2 * ( nutAF ) / sqrt(3)")
extrude "Extrude38" cut sketch "B M4 Nut Pocket 2" profile of L1 L2 L3 L4 L5 L6 no distance stored
sketch "B M4 Nut Pocket 3" plane through (-0.3536, -0.3536, 0) normal (0.7071, 0.7071, 0) x axis (0, 0, 1)
  line L1 (-20.549, -19.0274) -> (-18.4705, -22.6274)
  line L2 (-24.7059, -19.0274) -> (-20.549, -19.0274)
  line L3 (-26.7843, -22.6274) -> (-24.7059, -19.0274)
  line L4 (-24.7059, -26.2274) -> (-26.7843, -22.6274)
  line L5 (-20.549, -26.2274) -> (-24.7059, -26.2274)
  line L6 (-18.4705, -22.6274) -> (-20.549, -26.2274)
  circle C1 centre (-22.6274, -22.6274) radius 4.1569
  point P3 (-18.4705, -22.6274)
  point P4 (-20.549, -19.0274)
  point P5 (-24.7059, -19.0274)
  point P6 (-26.7843, -22.6274)
  point P7 (-24.7059, -26.2274)
  point P8 (-20.549, -26.2274)
  point P1 (0, 0)
  point P2 (-22.6274, -22.6274)
  coincident C1 P3
  coincident C1 P4
  coincident C1 P5
  coincident C1 P6
  coincident C1 P7
  coincident C1 P8
  equal L1 L2
  equal L1 L3
  equal L1 L4
  equal L1 L5
  equal L1 L6
  horizontal L2
  dimension "d848" distance P1 P2 = 22.6274 (= "abs(-mountCircle / ( 2 * sqrt(2) ))")
  dimension "d849" distance P1 P2 = 22.6274 (= "abs(-mountCircle / ( 2 * sqrt(2) ))")
  dimension "d850" diameter C1 = 8.3138 (= "2 * ( nutAF ) / sqrt(3)")
extrude "Extrude39" cut sketch "B M4 Nut Pocket 3" profile of L1 L2 L3 L4 L5 L6 no distance stored
sketch "B M4 Nut Pocket 4" plane through (-0.3536, -0.3536, 0) normal (0.7071, 0.7071, 0) x axis (0, 0, 1)
  line L1 (24.7059, -19.0274) -> (26.7843, -22.6274)
  line L2 (20.549, -19.0274) -> (24.7059, -19.0274)
  line L3 (18.4705, -22.6274) -> (20.549, -19.0274)
  line L4 (20.549, -26.2274) -> (18.4705, -22.6274)
  line L5 (24.7059, -26.2274) -> (20.549, -26.2274)
  line L6 (26.7843, -22.6274) -> (24.7059, -26.2274)
  circle C1 centre (22.6274, -22.6274) radius 4.1569
  point P3 (26.7843, -22.6274)
  point P4 (24.7059, -19.0274)
  point P5 (20.549, -19.0274)
  point P6 (18.4705, -22.6274)
  point P7 (20.549, -26.2274)
  point P8 (24.7059, -26.2274)
  point P1 (0, 0)
  point P2 (22.6274, -22.6274)
  coincident C1 P3
  coincident C1 P4
  coincident C1 P5
  coincident C1 P6
  coincident C1 P7
  coincident C1 P8
  equal L1 L2
  equal L1 L3
  equal L1 L4
  equal L1 L5
  equal L1 L6
  horizontal L2
  dimension "d853" distance P1 P2 = 22.6274 (= "abs(mountCircle / ( 2 * sqrt(2) ))")
  dimension "d854" distance P1 P2 = 22.6274 (= "abs(-mountCircle / ( 2 * sqrt(2) ))")
  dimension "d855" diameter C1 = 8.3138 (= "2 * ( nutAF ) / sqrt(3)")
extrude "Extrude40" cut sketch "B M4 Nut Pocket 4" profile of L1 L2 L3 L4 L5 L6 no distance stored
sketch "B Hub Service Slots" plane through (0, 0, 0) normal (0, 0, 1) x axis (1, 0, 0)
  line L1 (-30.4056, -12.0208) -> (-14.8492, 3.5355)
  line L2 (-12.0208, -30.4056) -> (-30.4056, -12.0208)
  line L3 (3.5355, -14.8492) -> (-12.0208, -30.4056)
  line L4 (-14.8492, 3.5355) -> (3.5355, -14.8492)
  point P1 (0, 0)
  point P2 (-14.8492, 3.5355)
  point P3 (-30.4056, -12.0208)
  point P4 (-12.0208, -30.4056)
  point P5 (3.5355, -14.8492)
  dimension "d858" distance P1 P2 = 14.8492 (= "abs(( -8 mm - 13 mm ) / sqrt(2))")
  dimension "d859" distance P1 P2 = 3.5355 (= "abs(( -8 mm + 13 mm ) / sqrt(2))")
  dimension "d860" distance P1 P3 = 30.4056 (= "abs(( -30 mm - 13 mm ) / sqrt(2))")
  dimension "d861" distance P1 P3 = 12.0208 (= "abs(( -30 mm + 13 mm ) / sqrt(2))")
  dimension "d862" distance P1 P4 = 12.0208 (= "abs(( -30 mm + 13 mm ) / sqrt(2))")
  dimension "d863" distance P1 P4 = 30.4056 (= "abs(( -30 mm - 13 mm ) / sqrt(2))")
  dimension "d864" distance P1 P5 = 3.5355 (= "abs(( -8 mm + 13 mm ) / sqrt(2))")
  dimension "d865" distance P1 P5 = 14.8492 (= "abs(( -8 mm - 13 mm ) / sqrt(2))")
extrude "Extrude41" cut sketch "B Hub Service Slots" distance 76 (= "mountOD")
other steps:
base_feature "Base Feature1" bodies "A Housing print"
base_feature "Base Feature1" bodies "B Moving Body print"
create_component "CreateComponent1"
reparent_decal "ReparentDecal1"
remove_body "RemoveBody1"
create_component "CreateComponent2"
reparent_decal "ReparentDecal2"
remove_body "RemoveBody2"
named bodies: "A Housing print", "B Moving Body print"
